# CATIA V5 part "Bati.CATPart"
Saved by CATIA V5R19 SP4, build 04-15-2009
Part number: Bati
Publications: "Diamètre axe"
Bounding box of the stored display mesh (mm): x -50 to 250, y -30 to 30, z -10 to 45
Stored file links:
  D:\thinkmotion-MPB\CIAO82010_JCF\PLANTECOSTE\0593\assemblage 593\Bati.CATPart
  D:\thinkmotion-MPB\CIAO82010_JCF\PLANTECOSTE\0593\assemblage 593\593-Plantecoste.CATProduct
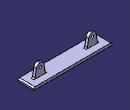
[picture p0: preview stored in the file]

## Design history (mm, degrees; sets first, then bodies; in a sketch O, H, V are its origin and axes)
External parameters (linked from other documents)
  External.Longueur.1 = 300 mm
Body1 (main body)
  Sketch1 on xy-plane, origin (0, 0, 0), H (1, 0, 0), V (0, 1, 0)
    line L1 (-50, 30) -> (250, 30)
    line L2 (250, 30) -> (250, -30)
    line L3 (250, -30) -> (-50, -30)
    line L4 (-50, -30) -> (-50, 30)
    length L4 = 60 {= External.Longueur.1 /5}
    length L1 = 300 {= External.Longueur.1}
    distance V L4 = 50 {= External.Longueur.1 /6}
    horizontal: L1 H, L3 H
    vertical: L2 V, L4 V
    symmetry: L1 L3 H
  Pad1: profile Sketch1, direction (0, 0, -1), length 10
  Sketch2 on zx-plane, origin (0, 0, 0), H (-1, 0, 0), V (0, 0, 1)
    construction line L1 (0, 0) -> (0, 128.0558)
    construction line L2 (-100, 0) -> (-100, 106.9596)
    point P2 (-100, 0)
    construction line L3 (0, 30) -> (-100, 30)
    point P4 (0, 30)
    point P5 (-100, 30)
    line L4 (20, 0) -> (14.811, 32.374)
    point P6 (20, 0)
    point P7 (14.811, 32.374)
    arc A1 centre (0, 30) radius 15 from (14.811, 32.374) to (0, 45) ccw
    point P8 (0, 45)
    circle A2 centre (0, 30) radius 5
    line L5 (20, 0) -> (0, 0)
    point P9 (0, 0)
    point P10 (-20, 0)
    line L6 (-20, 0) -> (0, 0)
    point P11 (-14.811, 32.374)
    line L7 (-20, 0) -> (-14.811, 32.374)
    point P12 (0, 45)
    arc A3 centre (0, 30) radius 15 from (-14.811, 32.374) to (0, 45) cw
    point P14 (-200, 0)
    construction line L8 through (-100, 0) direction (-1, 0)
    construction line L9 through (-200, 0) direction (0, 1)
    point P20 (-220, 0)
    point P21 (-214.811, 32.374)
    point P22 (-200, 45)
    point P23 (-200, 0)
    point P24 (-180, 0)
    point P25 (-185.189, 32.374)
    point P26 (-200, 45)
    line L10 (-220, 0) -> (-214.811, 32.374)
    arc A4 centre (-200, 30) radius 15 from (-214.811, 32.374) to (-200, 45) cw
    circle A5 centre (-200, 30) radius 5
    line L11 (-220, 0) -> (-200, 0)
    line L12 (-180, 0) -> (-200, 0)
    line L13 (-180, 0) -> (-185.189, 32.374)
    arc A6 centre (-200, 30) radius 15 from (-185.189, 32.374) to (-200, 45) ccw
    distance L2 L1 = 100 {= External.Longueur.1 /3}
    distance L3 H = 30 {= `Diamètre axe` *3}
    radius A1 = 15 {= `Diamètre axe` *1.5}
    distance P6 L1 = 20 {= External.Longueur.1 /15}
    radius A2 = 5 {= `Diamètre axe` /2}
    vertical: L1 V, L2 V
    coincidence: P2 H, P4 L1, P5 L2, P6 H, P8 L1, O P9, P8 P12, P14 P23, P22 P26
    horizontal: L3 H, L5 H
    tangency: A1 L4
    symmetry: O P9 L1, P6 P10 L1, L5 L6 L1, P7 P11 L1, L4 L7 L1, P8 P12 L1, A1 A3 L1, O P14 L2, H L8 L2, V L9 L2, P6 P20 L2, P7 P21 L2, P8 P22 L2, P9 P23 L2, P10 P24 L2, P11 P25 L2, P12 P26 L2, L4 L10 L2, A1 A4 L2, A2 A5 L2, L5 L11 L2, L6 L12 L2, L7 L13 L2, A3 A6 L2
  Pad2: profile Sketch2, direction (0, 1, 0), length 5 {= `Diamètre axe` /2}, opposite side length 5 {= `Diamètre axe` /2}
  Fillet1: radius 5 {= `Diamètre axe` /2}, on edge [face of Pad1 from Sketch1.L4 | start face of Pad1]; edge [face of Pad2 from Sketch2.L4 | start face of Pad1]; edge [start face of Pad1 | face of Pad2 from Sketch2.L7]; edge [face of Pad2 from Sketch2.L13 | start face of Pad1]; edge [start face of Pad1 | face of Pad2 from Sketch2.L10]; edge [face of Pad1 from Sketch1.L2 | start face of Pad1]
Relations
  `Diamètre axe` = `Diamètre axe` (deactivated)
